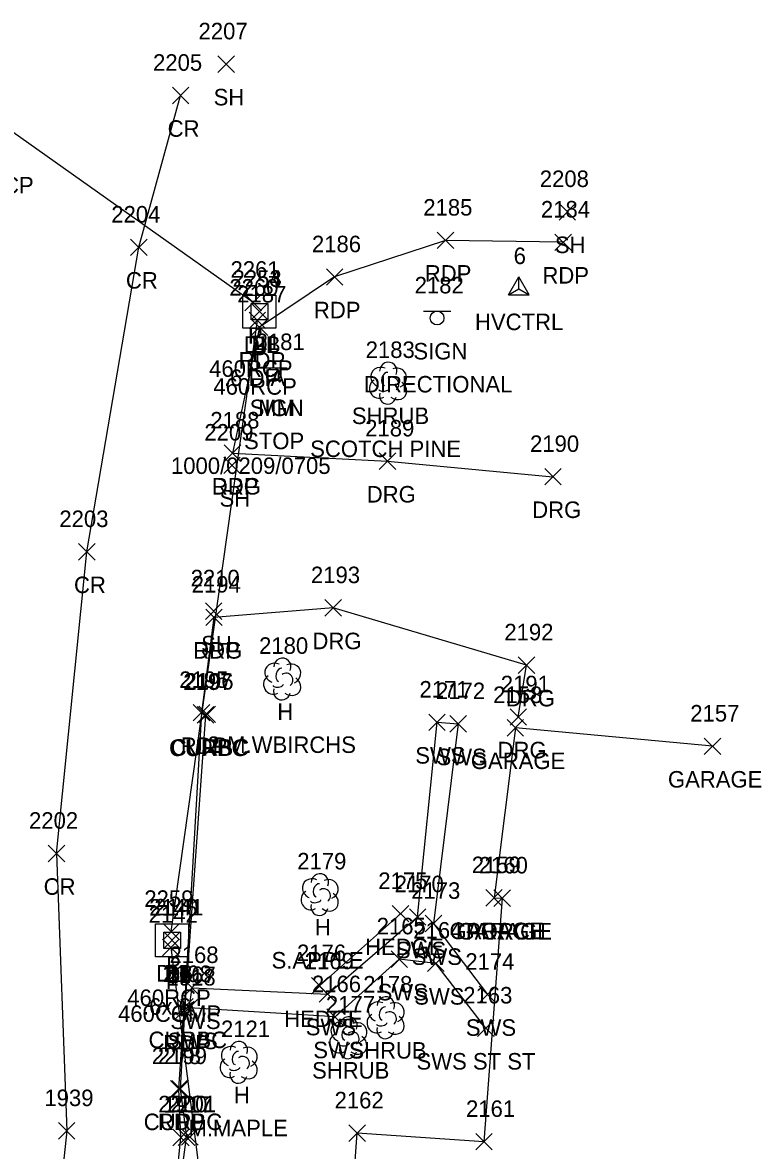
# Model space of a CAD drawing. Extents: x 462930 to 463548, y 29607 to 30453.
# Drawn here: x 463398.16 to 463425.44, y 30246.27 to 30287.89 of the extents above; entities that cross this region are included whole.
import ezdxf

# ---------------------------------------------------------------- set-up
doc = ezdxf.new("R2010")
doc.units = 0
for name, color, linetype in [('C_A', 7, 'Continuous'), ('C_I', 7, 'Continuous'), ('CPSM', 7, 'Continuous'), ('D_A', 7, 'Continuous'), ('D_C', 7, 'Continuous'), ('D_I', 7, 'Continuous'), ('D_TIC', 7, 'Continuous'), ('DCP', 7, 'Continuous'), ('DS', 7, 'Continuous'), ('L_A', 7, 'Continuous'), ('L_C', 7, 'Continuous'), ('L_I', 7, 'Continuous'), ('L_TIC', 7, 'Continuous'), ('LAHR', 7, 'Continuous'), ('LBC', 7, 'Continuous'), ('LBF', 7, 'Continuous'), ('LELB', 7, 'Continuous'), ('LSH', 7, 'Continuous'), ('LTD', 7, 'Continuous'), ('P_A', 7, 'Continuous'), ('P_I', 7, 'Continuous'), ('P_TIC', 7, 'Continuous'), ('PET', 7, 'Continuous'), ('PRC', 7, 'Continuous'), ('R_A', 7, 'Continuous'), ('R_I', 7, 'Continuous'), ('R_TIC', 7, 'Continuous'), ('RC', 7, 'Continuous'), ('RDG', 7, 'Continuous'), ('RSW', 7, 'Continuous'), ('S_A', 7, 'Continuous'), ('S_C', 7, 'Continuous'), ('S_I', 7, 'Continuous'), ('SRM', 7, 'Continuous'), ('SSGN', 7, 'Continuous')]:
    doc.layers.add(name, color=color, linetype=linetype)

msp = doc.modelspace()

# ---------------------------------------------------------------- linework, layer by layer
at = {"layer": 'CPSM'}
for p, q in [((463416.1, 30277.839), (463416.481, 30278.499)), ((463416.862, 30277.839), (463416.481, 30278.499)), ((463416.481, 30278.059), (463416.481, 30278.499)), ((463416.1, 30277.839), (463416.481, 30278.059)), ((463416.1, 30277.839), (463416.862, 30277.839)), ((463416.481, 30278.059), (463416.481, 30278.059)), ((463416.481, 30278.059), (463416.862, 30277.839))]:
    msp.add_line(p, q, dxfattribs=at)
at = {"layer": 'D_TIC'}
for points in [[(463406.367, 30277.25), (463406.977, 30277.86)], [(463406.977, 30277.25), (463406.367, 30277.86)], [(463406.602, 30276.915), (463407.212, 30277.525)], [(463407.212, 30276.915), (463406.602, 30277.525)], [(463406.524, 30276.591), (463407.134, 30277.201)], [(463407.134, 30276.591), (463406.524, 30277.201)], [(463403.346, 30254.034), (463403.956, 30254.644)], [(463403.956, 30254.034), (463403.346, 30254.644)], [(463403.331, 30253.447), (463403.941, 30254.057)], [(463403.941, 30253.447), (463403.331, 30254.057)], [(463403.37, 30253.717), (463403.98, 30254.327)], [(463403.98, 30253.717), (463403.37, 30254.327)]]:
    msp.add_lwpolyline(points, dxfattribs=at)
at = {"layer": 'DCP'}
for points in [[(463406.672, 30277.555), (463397.114, 30284.321)], [(463403.651, 30254.339), (463406.829, 30276.896)], [(463403.636, 30253.752), (463408.444, 30215.873)]]:
    msp.add_lwpolyline(points, dxfattribs=at)
at = {"layer": 'DS'}
for p, q in [((463406.296, 30277.829), (463407.515, 30277.829)), ((463406.296, 30276.61), (463406.296, 30277.829)), ((463407.515, 30277.829), (463407.515, 30276.61)), ((463406.601, 30276.915), (463406.601, 30277.524)), ((463406.601, 30277.524), (463407.21, 30277.524)), ((463407.21, 30277.524), (463407.21, 30276.915)), ((463407.21, 30276.915), (463406.601, 30276.915)), ((463406.907, 30277.22), (463406.907, 30277.22)), ((463406.907, 30277.22), (463406.907, 30277.22)), ((463407.515, 30276.61), (463406.296, 30276.61)), ((463403.073, 30254.626), (463404.292, 30254.626)), ((463403.073, 30253.407), (463403.073, 30254.626)), ((463404.292, 30254.626), (463404.292, 30253.407)), ((463403.378, 30253.712), (463403.378, 30254.321)), ((463403.378, 30254.321), (463403.987, 30254.321)), ((463403.684, 30254.017), (463403.684, 30254.017)), ((463403.684, 30254.017), (463403.684, 30254.017)), ((463403.987, 30254.321), (463403.987, 30253.712)), ((463403.987, 30253.712), (463403.378, 30253.712)), ((463404.292, 30253.407), (463403.073, 30253.407))]:
    msp.add_line(p, q, dxfattribs=at)
at = {"layer": 'L_TIC'}
for points in [[(463405.37, 30286.047), (463405.98, 30286.657)], [(463405.98, 30286.047), (463405.37, 30286.657)], [(463417.969, 30280.597), (463418.579, 30281.207)], [(463418.579, 30280.597), (463417.969, 30281.207)], [(463405.587, 30271.241), (463406.197, 30271.851)], [(463406.197, 30271.241), (463405.587, 30271.851)], [(463404.908, 30265.863), (463405.518, 30266.473)], [(463405.518, 30265.863), (463404.908, 30266.473)], [(463416.05, 30261.557), (463416.66, 30262.167)], [(463416.66, 30261.557), (463416.05, 30262.167)], [(463423.329, 30260.874), (463423.939, 30261.484)], [(463423.939, 30260.874), (463423.329, 30261.484)], [(463415.262, 30255.28), (463415.872, 30255.89)], [(463415.872, 30255.28), (463415.262, 30255.89)], [(463415.56, 30255.268), (463416.17, 30255.878)], [(463416.17, 30255.268), (463415.56, 30255.878)], [(463415.56, 30255.268), (463416.17, 30255.878)], [(463416.17, 30255.268), (463415.56, 30255.878)], [(463411.81, 30254.695), (463412.42, 30255.305)], [(463412.42, 30254.695), (463411.81, 30255.305)], [(463408.824, 30252.034), (463409.434, 30252.644)], [(463409.434, 30252.034), (463408.824, 30252.644)], [(463403.909, 30246.453), (463404.519, 30247.063)], [(463404.519, 30246.453), (463403.909, 30247.063)], [(463410.21, 30246.598), (463410.82, 30247.208)], [(463410.82, 30246.598), (463410.21, 30247.208)], [(463410.21, 30246.598), (463410.82, 30247.208)], [(463410.82, 30246.598), (463410.21, 30247.208)], [(463414.889, 30246.283), (463415.499, 30246.893)], [(463415.499, 30246.283), (463414.889, 30246.893)]]:
    msp.add_lwpolyline(points, dxfattribs=at)
at = {"layer": 'LAHR'}
msp.add_lwpolyline([(463412.115, 30255), (463409.129, 30252.339)], dxfattribs=at)
at = {"layer": 'LBC'}
for points in [[(463423.634, 30261.179), (463416.355, 30261.862), (463415.567, 30255.585), (463415.865, 30255.573)], [(463418.676, 30239.314), (463410.016, 30240.051), (463410.515, 30246.903)]]:
    msp.add_lwpolyline(points, dxfattribs=at)
at = {"layer": 'LBF'}
msp.add_lwpolyline([(463415.865, 30255.573), (463415.194, 30246.588), (463410.515, 30246.903)], dxfattribs=at)
at = {"layer": 'LELB'}
msp.add_lwpolyline([(463403.731, 30243.164), (463404.214, 30246.758)], dxfattribs=at)
at = {"layer": 'LSH'}
for p, q in [((463411.649, 30274.594), (463411.649, 30274.594)), ((463411.649, 30274.594), (463411.649, 30274.594)), ((463411.559, 30251.178), (463411.559, 30251.178)), ((463411.559, 30251.178), (463411.559, 30251.178)), ((463410.181, 30250.44), (463410.181, 30250.44)), ((463410.181, 30250.44), (463410.181, 30250.44))]:
    msp.add_line(p, q, dxfattribs=at)
for centre in [(463411.663, 30275.031), (463411.573, 30251.615), (463410.195, 30250.877)]:
    msp.add_arc(centre, 0.319, 335.5272, 180.9563, dxfattribs=at)
for centre, major_axis, ratio, start_param, end_param in [((463411.408, 30274.797), (0.369, -0.156), 0.895232, 1.570796, 4.712389), ((463411.966, 30274.772), (-0.348, -0.147), 0.949671, 1.570796, 4.712389), ((463411.585, 30274.734), (-0.063, -0.241), 0.645439, 3.141593, 6.283185), ((463411.801, 30274.543), (-0.152, 0.203), 0.989748, 3.141593, 6.283185), ((463411.319, 30274.378), (0.178, -0.317), 0.959034, 3.141593, 6.283185), ((463411.509, 30274.365), (-0.19, -0.025), 0.423636, 0, 3.141593), ((463411.954, 30274.34), (-0.332, 0.241), 0.841452, 1.570796, 4.712389), ((463411.649, 30274.137), (0.081, 0.323), 0.942809, 1.570796, 4.712389), ((463411.318, 30251.381), (0.369, -0.156), 0.895232, 1.570796, 4.712389), ((463411.495, 30251.318), (-0.063, -0.241), 0.645439, 3.141593, 6.283185), ((463411.876, 30251.356), (-0.348, -0.147), 0.949671, 1.570796, 4.712389), ((463409.94, 30250.643), (0.369, -0.156), 0.895232, 1.570796, 4.712389), ((463411.229, 30250.962), (0.178, -0.317), 0.959034, 3.141593, 6.283185), ((463411.711, 30251.127), (-0.152, 0.203), 0.989748, 3.141593, 6.283185), ((463411.864, 30250.924), (-0.332, 0.241), 0.841452, 1.570796, 4.712389), ((463410.117, 30250.58), (-0.063, -0.241), 0.645439, 3.141593, 6.283185), ((463410.333, 30250.389), (-0.152, 0.203), 0.989748, 3.141593, 6.283185), ((463410.498, 30250.618), (-0.348, -0.147), 0.949671, 1.570796, 4.712389), ((463411.559, 30250.721), (0.081, 0.323), 0.942809, 1.570796, 4.712389), ((463411.419, 30250.949), (-0.19, -0.025), 0.423636, 0, 3.141593), ((463409.851, 30250.224), (0.178, -0.317), 0.959034, 3.141593, 6.283185), ((463410.041, 30250.211), (-0.19, -0.025), 0.423636, 0, 3.141593), ((463410.486, 30250.186), (-0.332, 0.241), 0.841452, 1.570796, 4.712389), ((463410.181, 30249.983), (0.081, 0.323), 0.942809, 1.570796, 4.712389)]:
    msp.add_ellipse(centre, major_axis=major_axis, ratio=ratio, start_param=start_param, end_param=end_param, dxfattribs=at)
at = {"layer": 'LTD'}
for p, q in [((463407.739, 30263.676), (463407.739, 30263.676)), ((463407.739, 30263.676), (463407.739, 30263.676)), ((463409.124, 30255.721), (463409.124, 30255.721)), ((463409.124, 30255.721), (463409.124, 30255.721)), ((463406.133, 30249.533), (463406.133, 30249.533)), ((463406.133, 30249.533), (463406.133, 30249.533))]:
    msp.add_line(p, q, dxfattribs=at)
for centre in [(463407.753, 30264.113), (463409.138, 30256.158), (463406.147, 30249.97)]:
    msp.add_arc(centre, 0.319, 335.5272, 180.9563, dxfattribs=at)
for centre, major_axis, ratio, start_param, end_param in [((463407.498, 30263.879), (0.369, -0.156), 0.895232, 1.570796, 4.712389), ((463407.675, 30263.816), (-0.063, -0.241), 0.645439, 3.141593, 6.283185), ((463408.056, 30263.854), (-0.348, -0.147), 0.949671, 1.570796, 4.712389), ((463407.409, 30263.46), (0.178, -0.317), 0.959034, 3.141593, 6.283185), ((463407.891, 30263.625), (-0.152, 0.203), 0.989748, 3.141593, 6.283185), ((463408.044, 30263.422), (-0.332, 0.241), 0.841452, 1.570796, 4.712389), ((463407.739, 30263.219), (0.081, 0.323), 0.942809, 1.570796, 4.712389), ((463407.599, 30263.447), (-0.19, -0.025), 0.423636, 0, 3.141593), ((463408.883, 30255.924), (0.369, -0.156), 0.895232, 1.570796, 4.712389), ((463409.06, 30255.861), (-0.063, -0.241), 0.645439, 3.141593, 6.283185), ((463409.441, 30255.899), (-0.348, -0.147), 0.949671, 1.570796, 4.712389), ((463408.794, 30255.505), (0.178, -0.317), 0.959034, 3.141593, 6.283185), ((463409.276, 30255.67), (-0.152, 0.203), 0.989748, 3.141593, 6.283185), ((463409.429, 30255.467), (-0.332, 0.241), 0.841452, 1.570796, 4.712389), ((463409.124, 30255.264), (0.081, 0.323), 0.942809, 1.570796, 4.712389), ((463408.984, 30255.492), (-0.19, -0.025), 0.423636, 0, 3.141593), ((463405.892, 30249.736), (0.369, -0.156), 0.895232, 1.570796, 4.712389), ((463406.069, 30249.673), (-0.063, -0.241), 0.645439, 3.141593, 6.283185), ((463406.45, 30249.711), (-0.348, -0.147), 0.949671, 1.570796, 4.712389), ((463405.803, 30249.317), (0.178, -0.317), 0.959034, 3.141593, 6.283185), ((463406.285, 30249.482), (-0.152, 0.203), 0.989748, 3.141593, 6.283185), ((463406.438, 30249.279), (-0.332, 0.241), 0.841452, 1.570796, 4.712389), ((463406.133, 30249.076), (0.081, 0.323), 0.942809, 1.570796, 4.712389), ((463405.993, 30249.304), (-0.19, -0.025), 0.423636, 0, 3.141593)]:
    msp.add_ellipse(centre, major_axis=major_axis, ratio=ratio, start_param=start_param, end_param=end_param, dxfattribs=at)
at = {"layer": 'P_TIC'}
for points in [[(463403.69, 30284.888), (463404.3, 30285.498)], [(463404.3, 30284.888), (463403.69, 30285.498)], [(463402.149, 30279.287), (463402.759, 30279.897)], [(463402.759, 30279.287), (463402.149, 30279.897)], [(463413.471, 30279.543), (463414.081, 30280.153)], [(463414.081, 30279.543), (463413.471, 30280.153)], [(463417.814, 30279.472), (463418.424, 30280.082)], [(463418.424, 30279.472), (463417.814, 30280.082)], [(463409.377, 30278.191), (463409.987, 30278.801)], [(463409.987, 30278.191), (463409.377, 30278.801)], [(463406.6, 30276.336), (463407.21, 30276.946)], [(463407.21, 30276.336), (463406.6, 30276.946)], [(463405.608, 30271.687), (463406.218, 30272.297)], [(463406.218, 30271.687), (463405.608, 30272.297)], [(463400.231, 30268.05), (463400.841, 30268.66)], [(463400.841, 30268.05), (463400.231, 30268.66)], [(463404.921, 30265.632), (463405.531, 30266.242)], [(463405.531, 30265.632), (463404.921, 30266.242)], [(463404.46, 30262.114), (463405.07, 30262.724)], [(463405.07, 30262.114), (463404.46, 30262.724)], [(463399.111, 30256.918), (463399.721, 30257.528)], [(463399.721, 30256.918), (463399.111, 30257.528)], [(463403.818, 30251.129), (463404.428, 30251.739)], [(463404.428, 30251.129), (463403.818, 30251.739)], [(463403.621, 30248.233), (463404.231, 30248.843)], [(463404.231, 30248.233), (463403.621, 30248.843)], [(463399.484, 30246.682), (463400.094, 30247.292)], [(463400.094, 30246.682), (463399.484, 30247.292)], [(463403.702, 30246.435), (463404.312, 30247.045)], [(463404.312, 30246.435), (463403.702, 30247.045)]]:
    msp.add_lwpolyline(points, dxfattribs=at)
at = {"layer": 'PET'}
for points in [[(463418.119, 30279.777), (463413.776, 30279.848), (463409.682, 30278.496), (463406.905, 30276.641), (463405.913, 30271.992)], [(463405.226, 30265.937), (463404.765, 30262.419)], [(463404.765, 30262.419), (463404.123, 30251.434)], [(463357.128, 30146.779), (463364.23, 30160.089), (463372.211, 30170.687), (463380.439, 30181.089), (463388.986, 30192.495), (463395.438, 30204.072), (463399.65, 30216.413), (463402.389, 30229.411), (463403.525, 30242.02), (463404.007, 30246.74), (463403.926, 30248.538), (463404.123, 30251.434)]]:
    msp.add_lwpolyline(points, dxfattribs=at)
at = {"layer": 'PRC'}
for points in [[(463399.416, 30257.223), (463400.536, 30268.355), (463402.454, 30279.592), (463403.995, 30285.193)], [(463399.416, 30257.223), (463399.789, 30246.987)], [(463399.789, 30246.987), (463397.991, 30230.027), (463395.304, 30217.172), (463391.095, 30206.312), (463384.492, 30195.113), (463376.573, 30184.227), (463367.848, 30173.371), (463360.659, 30162.372), (463353.283, 30149.309)]]:
    msp.add_lwpolyline(points, dxfattribs=at)
at = {"layer": 'R_TIC'}
for points in [[(463405.608, 30271.687), (463406.218, 30272.297)], [(463406.218, 30271.687), (463405.608, 30272.297)], [(463411.328, 30271.393), (463411.938, 30272.003)], [(463411.938, 30271.393), (463411.328, 30272.003)], [(463417.438, 30270.822), (463418.048, 30271.432)], [(463418.048, 30270.822), (463417.438, 30271.432)], [(463409.323, 30265.98), (463409.933, 30266.59)], [(463409.933, 30265.98), (463409.323, 30266.59)], [(463404.921, 30265.632), (463405.531, 30266.242)], [(463405.531, 30265.632), (463404.921, 30266.242)], [(463416.464, 30263.869), (463417.074, 30264.479)], [(463417.074, 30263.869), (463416.464, 30264.479)], [(463404.608, 30262.037), (463405.218, 30262.647)], [(463405.218, 30262.037), (463404.608, 30262.647)], [(463404.67, 30262.051), (463405.28, 30262.661)], [(463405.28, 30262.051), (463404.67, 30262.661)], [(463413.157, 30261.758), (463413.767, 30262.368)], [(463413.767, 30261.758), (463413.157, 30262.368)], [(463413.94, 30261.7), (463414.55, 30262.31)], [(463414.55, 30261.7), (463413.94, 30262.31)], [(463416.159, 30261.953), (463416.769, 30262.563)], [(463416.769, 30261.953), (463416.159, 30262.563)], [(463412.44, 30254.576), (463413.05, 30255.186)], [(463413.05, 30254.576), (463412.44, 30255.186)], [(463413.024, 30254.331), (463413.634, 30254.941)], [(463413.634, 30254.331), (463413.024, 30254.941)], [(463411.765, 30253.021), (463412.375, 30253.631)], [(463412.375, 30253.021), (463411.765, 30253.631)], [(463413.116, 30252.864), (463413.726, 30253.474)], [(463413.726, 30252.864), (463413.116, 30253.474)], [(463404.113, 30251.963), (463404.723, 30252.573)], [(463404.723, 30251.963), (463404.113, 30252.573)], [(463409.112, 30251.732), (463409.722, 30252.342)], [(463409.722, 30251.732), (463409.112, 30252.342)], [(463415.023, 30251.714), (463415.633, 30252.324)], [(463415.633, 30251.714), (463415.023, 30252.324)], [(463403.852, 30251.26), (463404.462, 30251.87)], [(463404.462, 30251.26), (463403.852, 30251.87)], [(463404.008, 30251.221), (463404.618, 30251.831)], [(463404.618, 30251.221), (463404.008, 30251.831)], [(463409.391, 30250.886), (463410.001, 30251.496)], [(463410.001, 30250.886), (463409.391, 30251.496)], [(463414.96, 30250.469), (463415.57, 30251.079)], [(463415.57, 30250.469), (463414.96, 30251.079)], [(463403.674, 30248.234), (463404.284, 30248.844)], [(463404.284, 30248.234), (463403.674, 30248.844)], [(463403.909, 30246.453), (463404.519, 30247.063)], [(463404.519, 30246.453), (463403.909, 30247.063)], [(463404.031, 30246.457), (463404.641, 30247.067)], [(463404.641, 30246.457), (463404.031, 30247.067)]]:
    msp.add_lwpolyline(points, dxfattribs=at)
at = {"layer": 'RC'}
msp.add_lwpolyline([(463404.975, 30262.356), (463404.913, 30262.342), (463404.157, 30251.565), (463403.979, 30248.539), (463404.214, 30246.758), (463404.336, 30246.762)], dxfattribs=at)
at = {"layer": 'RDG'}
for points in [[(463405.913, 30271.992), (463411.633, 30271.698), (463417.743, 30271.127)], [(463416.464, 30262.258), (463416.769, 30264.174), (463409.628, 30266.285), (463405.226, 30265.937)]]:
    msp.add_lwpolyline(points, dxfattribs=at)
at = {"layer": 'RSW'}
msp.add_lwpolyline([(463415.265, 30250.774), (463413.421, 30253.169), (463412.07, 30253.326), (463409.696, 30251.191), (463404.313, 30251.526), (463404.418, 30252.268), (463409.417, 30252.037), (463412.745, 30254.881), (463413.462, 30262.063), (463414.245, 30262.005), (463413.329, 30254.636), (463415.328, 30252.019)], dxfattribs=at)
at = {"layer": 'SRM'}
msp.add_lwpolyline([(463407.221, 30275.077), (463407.603, 30275.077), (463407.603, 30274.695), (463407.221, 30274.695)], close=True, dxfattribs=at)
msp.add_circle((463407.412, 30274.886), 0.0254, dxfattribs=at)
at = {"layer": 'SSGN'}
for p, q in [((463412.961, 30277.237), (463413.977, 30277.237)), ((463413.463, 30276.983), (463413.463, 30276.983)), ((463406.916, 30275.146), (463407.932, 30275.146)), ((463407.418, 30274.892), (463407.418, 30274.892))]:
    msp.add_line(p, q, dxfattribs=at)
for centre in [(463413.463, 30276.983), (463407.418, 30274.892)]:
    msp.add_circle(centre, 0.254, dxfattribs=at)

# ---------------------------------------------------------------- texts
at = {"layer": 'C_A'}
msp.add_text('HVCTRL', height=0.6096, dxfattribs=at).set_placement((463414.863, 30276.535))
at = {"layer": 'C_I'}
msp.add_text('6', height=0.61, dxfattribs=at).set_placement((463416.291, 30278.973))
at = {"layer": 'D_A'}
for s, height, p in [('P', 0.61, (463406.482, 30276.031)), ('DIB', 0.6096, (463406.329, 30275.696)), ('DI', 0.6096, (463406.619, 30275.696)), ('P', 0.61, (463406.639, 30275.372)), ('P', 0.61, (463403.461, 30252.815)), ('DIB', 0.6096, (463403.097, 30252.498)), ('DI', 0.6096, (463403.396, 30252.493)), ('P', 0.61, (463403.446, 30252.228))]:
    msp.add_text(s, height=height, dxfattribs=at).set_placement(p)
at = {"layer": 'D_C'}
for s, p in [('460RCP', (463395.489, 30281.578)), ('460RCP', (463405.047, 30274.812)), ('460RCP', (463405.204, 30274.153)), ('.6 DIA', (463405.594, 30274.477)), ('460RCP', (463402.026, 30251.596)), ('.6x.6', (463402.606, 30251.274)), ('460CGMP', (463401.685, 30251.009))]:
    msp.add_text(s, height=0.6096, dxfattribs=at).set_placement(p)
at = {"layer": 'D_I'}
for s, p in [('2261', (463405.837, 30278.469)), ('2253', (463405.913, 30278.134)), ('2254', (463405.913, 30278.134)), ('2260', (463405.795, 30277.81)), ('2259', (463402.655, 30255.253)), ('2142', (463402.815, 30254.666)), ('2140', (463402.837, 30254.931)), ('2141', (463403.027, 30254.936))]:
    msp.add_text(s, height=0.6096, dxfattribs=at).set_placement(p)
at = {"layer": 'L_A'}
for s, height, p in [('SH', 0.6096, (463405.214, 30284.828)), ('SH', 0.6096, (463417.813, 30279.378)), ('SHRUB', 0.6096, (463410.317, 30273.07)), ('SH', 0.6096, (463405.431, 30270.022)), ('SH', 0.6096, (463404.752, 30264.644)), ('H', 0.61, (463407.566, 30262.152)), ('GARAGE', 0.6096, (463414.709, 30260.338)), ('GARAGE', 0.6096, (463421.988, 30259.655)), ('H', 0.61, (463408.951, 30254.197)), ('GARAGE', 0.6096, (463413.921, 30254.061)), ('GARAGE', 0.6096, (463414.219, 30254.049)), ('PORCH', 0.6096, (463414.531, 30254.049)), ('HEDGE', 0.6096, (463410.805, 30253.476)), ('HEDGE', 0.6096, (463407.819, 30250.815)), ('SHRUB', 0.6096, (463410.227, 30249.654)), ('SHRUB', 0.6096, (463408.849, 30248.916)), ('H', 0.61, (463405.96, 30248.009))]:
    msp.add_text(s, height=height, dxfattribs=at).set_placement(p)
at = {"layer": 'L_C'}
for s, p in [('SCOTCH PINE', (463408.779, 30271.851)), ('2-M.WBIRCHS', (463404.989, 30260.933)), ('S.APPLE', (463407.353, 30252.978)), ('M.MAPLE', (463404.285, 30246.79))]:
    msp.add_text(s, height=0.6096, dxfattribs=at).set_placement(p)
at = {"layer": 'L_I'}
for s, p in [('2207', (463404.657, 30287.266)), ('2208', (463417.256, 30281.816)), ('2183', (463410.828, 30275.508)), ('2209', (463404.872, 30272.46)), ('2210', (463404.366, 30267.082)), ('2180', (463406.892, 30264.59)), ('2158', (463415.534, 30262.776)), ('2157', (463422.813, 30262.093)), ('2179', (463408.301, 30256.635)), ('2159', (463414.744, 30256.499)), ('2160', (463415.003, 30256.487)), ('2160', (463415.003, 30256.487)), ('2175', (463411.294, 30255.914)), ('2176', (463408.291, 30253.253)), ('2178', (463410.738, 30252.092)), ('2177', (463409.36, 30251.354)), ('2121', (463405.485, 30250.447)), ('2200', (463403.17, 30247.672)), ('2162', (463409.68, 30247.817)), ('2162', (463409.68, 30247.817)), ('2161', (463414.532, 30247.502))]:
    msp.add_text(s, height=0.6096, dxfattribs=at).set_placement(p)
at = {"layer": 'P_A'}
for s, p in [('CR', (463403.517, 30283.669)), ('RDP', (463413.01, 30278.324)), ('CR', (463401.976, 30278.068)), ('RDP', (463417.353, 30278.253)), ('RDP', (463408.916, 30276.972)), ('RDP', (463406.139, 30275.117)), ('RDP', (463405.147, 30270.468)), ('CR', (463400.058, 30266.831)), ('RDP', (463404.46, 30264.413)), ('RDP', (463403.999, 30260.895)), ('CR', (463398.938, 30255.699)), ('RDP', (463403.357, 30249.91)), ('RDP', (463403.16, 30247.014))]:
    msp.add_text(s, height=0.6096, dxfattribs=at).set_placement(p)
at = {"layer": 'P_I'}
for s, p in [('2205', (463402.977, 30286.107)), ('2204', (463401.436, 30280.506)), ('2185', (463412.955, 30280.762)), ('2184', (463417.298, 30280.691)), ('2186', (463408.844, 30279.41)), ('2187', (463406.084, 30277.555)), ('2188', (463405.092, 30272.906)), ('2203', (463399.518, 30269.269)), ('2194', (463404.405, 30266.851)), ('2195', (463403.944, 30263.333)), ('2202', (463398.398, 30258.137)), ('1918', (463403.475, 30252.348)), ('2278', (463402.932, 30249.452)), ('1939', (463398.966, 30247.901)), ('1917', (463403.359, 30247.654))]:
    msp.add_text(s, height=0.6096, dxfattribs=at).set_placement(p)
at = {"layer": 'R_A'}
for s, p in [('DRG', (463405.147, 30270.468)), ('DRG', (463410.867, 30270.174)), ('DRG', (463416.977, 30269.603)), ('DRG', (463408.862, 30264.761)), ('DRG', (463404.46, 30264.413)), ('DRG', (463416.003, 30262.65)), ('CURBC', (463403.629, 30260.832)), ('CURBC', (463403.567, 30260.818)), ('SWS', (463412.66, 30260.539)), ('SWS', (463413.443, 30260.481)), ('DRG', (463415.698, 30260.734)), ('SWS', (463411.943, 30253.357)), ('SWS', (463412.527, 30253.112)), ('SWS', (463411.268, 30251.802)), ('SWS', (463412.619, 30251.645)), ('SWS', (463403.616, 30250.744)), ('SWS', (463408.615, 30250.513)), ('SWS', (463414.526, 30250.495)), ('CURBC', (463402.811, 30250.041)), ('SWS', (463403.511, 30250.002)), ('SWS', (463408.894, 30249.667)), ('SWS ST ST', (463412.704, 30249.25)), ('CURBC', (463402.633, 30247.015))]:
    msp.add_text(s, height=0.6096, dxfattribs=at).set_placement(p)
at = {"layer": 'R_I'}
for s, p in [('2188', (463405.092, 30272.906)), ('2189', (463410.81, 30272.612)), ('2190', (463416.896, 30272.041)), ('2193', (463408.807, 30267.199)), ('2194', (463404.405, 30266.851)), ('2192', (463415.948, 30265.088)), ('2197', (463404.092, 30263.256)), ('2196', (463404.137, 30263.27)), ('2171', (463412.814, 30262.977)), ('2172', (463413.424, 30262.919)), ('2191', (463415.816, 30263.172)), ('2170', (463411.898, 30255.795)), ('2173', (463412.508, 30255.55)), ('2165', (463411.235, 30254.24)), ('2164', (463412.586, 30254.083)), ('2168', (463403.583, 30253.182)), ('2169', (463408.579, 30252.951)), ('2174', (463414.507, 30252.933)), ('2198', (463403.336, 30252.479)), ('2167', (463403.478, 30252.44)), ('2166', (463408.844, 30252.105)), ('2163', (463414.43, 30251.688)), ('2199', (463403.156, 30249.453)), ('2200', (463403.17, 30247.672)), ('2201', (463403.491, 30247.676))]:
    msp.add_text(s, height=0.6096, dxfattribs=at).set_placement(p)
at = {"layer": 'S_A'}
for s, p in [('SIGN', (463412.591, 30275.453)), ('SIGN', (463406.546, 30273.362)), ('MM', (463406.86, 30273.362))]:
    msp.add_text(s, height=0.6096, dxfattribs=at).set_placement(p)
at = {"layer": 'S_C'}
for s, p in [('DIRECTIONAL', (463410.764, 30274.234)), ('STOP', (463406.339, 30272.143)), ('1000/0209/0705', (463403.639, 30271.228))]:
    msp.add_text(s, height=0.6096, dxfattribs=at).set_placement(p)
at = {"layer": 'S_I'}
for s, p in [('2182', (463412.636, 30277.891)), ('2181', (463406.764, 30275.8)), ('2181', (463406.764, 30275.8))]:
    msp.add_text(s, height=0.6096, dxfattribs=at).set_placement(p)

doc.saveas('drawing.dxf')
